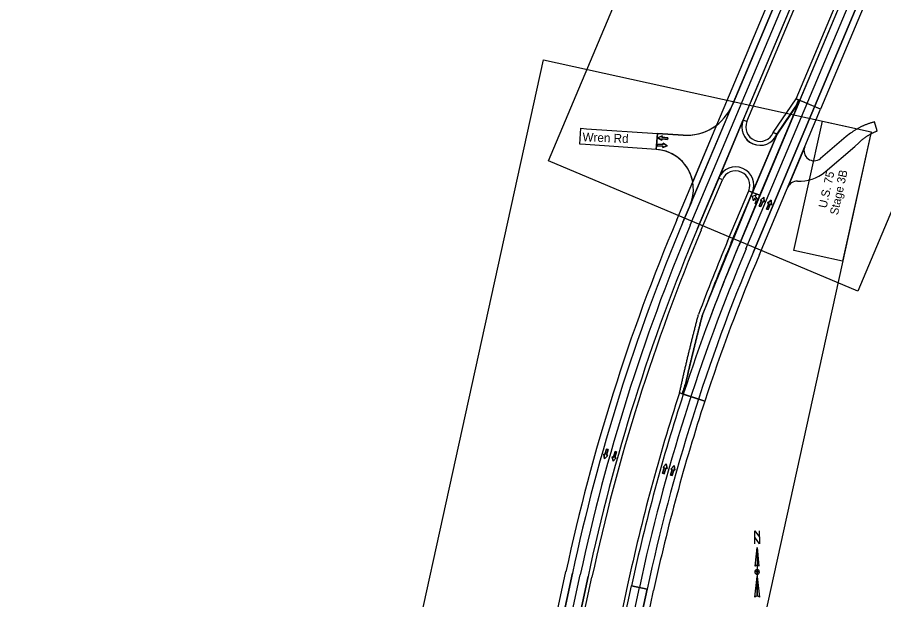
# Model space of a CAD drawing. Extents: x 14104283 to 14120882, y 8635219 to 8671666.
# Drawn here: x 14108141 to 14109445, y 8644864 to 8645740 of the extents above; entities that cross this region are included whole.
import ezdxf

# ---------------------------------------------------------------- set-up
doc = ezdxf.new("R2010")
doc.units = 0
for name, color, linetype in [('Cell', 7, 'Continuous'), ('dsnCellsNorthArrow', 7, 'Continuous'), ('dsnNonPlotable', 7, 'Continuous'), ('dsnPaintExistingBrokenLaneLineWhite', 7, 'Continuous'), ('dsnPaintExistingEdgeLineLeftYellow', 7, 'Continuous'), ('dsnPaintExistingEdgeLineRightWhite', 7, 'Continuous'), ('dsnPaintExistingLaneLineWhite', 7, 'Continuous'), ('dsnShadingGranular', 7, 'Continuous'), ('dsnShadingPaved', 7, 'Continuous'), ('dsnStgShadingPrevPav', 7, 'Continuous'), ('dsnTextFinalPlan', 7, 'Continuous'), ('dsnTextOverlapEven', 7, 'Continuous')]:
    doc.layers.add(name, color=color, linetype=linetype)

msp = doc.modelspace()

# ---------------------------------------------------------------- linework, layer by layer
at = {"layer": 'Cell'}
for p, q in [((14109250.7, 8645466.9), (14109250.4, 8645467)), ((14109251.5, 8645469.4), (14109251.7, 8645469.4))]:
    msp.add_line(p, q, dxfattribs=at)
for points in [[(14109119.8, 8645558.6), (14109119.6, 8645556.1), (14109110.9, 8645556.8), (14109110.7, 8645554.9), (14109104.8, 8645558.6), (14109111.2, 8645561.2), (14109111.1, 8645559.3)], [(14109103.8, 8645546.5), (14109104, 8645549), (14109112.7, 8645548.3), (14109112.9, 8645550.1), (14109118.9, 8645546.5), (14109112.4, 8645543.9), (14109112.5, 8645545.8)], [(14109259.9, 8645454.9), (14109257.6, 8645455.8), (14109260.9, 8645463.9), (14109259.2, 8645464.6), (14109264.4, 8645469.2), (14109265, 8645462.3), (14109263.2, 8645463)], [(14109270.7, 8645450.4), (14109268.4, 8645451.3), (14109271.7, 8645459.4), (14109270, 8645460.1), (14109275.2, 8645464.7), (14109275.7, 8645457.7), (14109274, 8645458.5)], [(14109027.8, 8645090.4), (14109030.2, 8645089.7), (14109027.7, 8645081.3), (14109029.5, 8645080.7), (14109024.8, 8645075.6), (14109023.5, 8645082.5), (14109025.3, 8645082)], [(14109040.4, 8645086.8), (14109042.8, 8645086.1), (14109040.3, 8645077.7), (14109042.1, 8645077.2), (14109037.4, 8645072.1), (14109036.1, 8645078.9), (14109037.9, 8645078.4)], [(14109114.4, 8645053.2), (14109112, 8645054), (14109114.5, 8645062.3), (14109112.7, 8645062.9), (14109117.4, 8645068), (14109118.7, 8645061.1), (14109116.9, 8645061.6)], [(14109126.3, 8645050.6), (14109123.9, 8645051.3), (14109126.3, 8645059.7), (14109124.5, 8645060.3), (14109129.3, 8645065.4), (14109130.5, 8645058.5), (14109128.7, 8645059)]]:
    msp.add_lwpolyline(points, close=True, dxfattribs=at)
for points in [[(14109111.1, 8645559.3), (14109111.2, 8645561.2), (14109104.8, 8645558.6), (14109110.7, 8645554.9), (14109110.9, 8645556.8), (14109119.6, 8645556.1), (14109119.8, 8645558.6), (14109111.1, 8645559.3)], [(14109112.5, 8645545.8), (14109112.4, 8645543.9), (14109118.9, 8645546.5), (14109112.9, 8645550.1), (14109112.7, 8645548.3), (14109104, 8645549), (14109103.8, 8645546.5), (14109112.5, 8645545.8)], [(14109247.3, 8645470.5), (14109253, 8645472.8), (14109251.5, 8645469.4)], [(14109247.3, 8645470.5), (14109253, 8645472.8), (14109251.5, 8645469.4)], [(14109250.4, 8645467), (14109248.8, 8645463.7), (14109247.3, 8645470.5)], [(14109250.4, 8645467), (14109248.8, 8645463.7), (14109247.3, 8645470.5)], [(14109250.7, 8645466.9), (14109250.4, 8645467)], [(14109251.5, 8645469.4), (14109251.7, 8645469.4)], [(14109263.2, 8645463), (14109265, 8645462.3), (14109264.4, 8645469.2), (14109259.2, 8645464.6), (14109260.9, 8645463.9), (14109257.6, 8645455.8), (14109259.9, 8645454.9), (14109263.2, 8645463)], [(14109274, 8645458.5), (14109275.7, 8645457.7), (14109275.2, 8645464.7), (14109270, 8645460.1), (14109271.7, 8645459.4), (14109268.4, 8645451.3), (14109270.7, 8645450.4), (14109274, 8645458.5)], [(14109254.3, 8645462.6), (14109252.9, 8645459.2), (14109251.5, 8645459.8), (14109252.5, 8645462.2)], [(14109254.3, 8645462.6), (14109252.9, 8645459.2), (14109251.5, 8645459.8), (14109252.5, 8645462.2)], [(14109025.3, 8645082), (14109023.5, 8645082.5), (14109024.8, 8645075.6), (14109029.5, 8645080.7), (14109027.7, 8645081.3), (14109030.2, 8645089.7), (14109027.8, 8645090.4), (14109025.3, 8645082)], [(14109037.9, 8645078.4), (14109036.1, 8645078.9), (14109037.4, 8645072.1), (14109042.1, 8645077.2), (14109040.3, 8645077.7), (14109042.8, 8645086.1), (14109040.4, 8645086.8), (14109037.9, 8645078.4)], [(14109116.9, 8645061.6), (14109118.7, 8645061.1), (14109117.4, 8645068), (14109112.7, 8645062.9), (14109114.5, 8645062.3), (14109112, 8645054), (14109114.4, 8645053.2), (14109116.9, 8645061.6)], [(14109128.7, 8645059), (14109130.5, 8645058.5), (14109129.3, 8645065.4), (14109124.5, 8645060.3), (14109126.3, 8645059.7), (14109123.9, 8645051.3), (14109126.3, 8645050.6), (14109128.7, 8645059)]]:
    msp.add_lwpolyline(points, dxfattribs=at)
for centre, major_axis in [((14109249.3, 8645463.5), (-1.38, -3.41)), ((14109249.3, 8645463.5), (-1.38, -3.41)), ((14109249.7, 8645464.5), (-1.97, -4.87)), ((14109249.7, 8645464.5), (-1.97, -4.87))]:
    msp.add_ellipse(centre, major_axis=major_axis, ratio=0.9474, start_param=1.570796, end_param=3.141593, dxfattribs=at)
at = {"layer": 'dsnCellsNorthArrow'}
for p, q in [((14109254.3, 8644942.2), (14109257.1, 8644914.1)), ((14109254.3, 8644942.2), (14109254.3, 8644869)), ((14109251.5, 8644914.1), (14109251.5, 8644914.1)), ((14109251.6, 8644914.3), (14109252.1, 8644914.9)), ((14109250.8, 8644867.6), (14109254.3, 8644898.6)), ((14109254.3, 8644902.1), (14109254.3, 8644902.1))]:
    msp.add_line(p, q, dxfattribs=at)
msp.add_lwpolyline([(14109257.8, 8644947.9), (14109250.8, 8644957.7), (14109250.8, 8644967.6), (14109257.8, 8644957.7)], close=True, dxfattribs=at)
for points in [[(14109250.8, 8644947.9), (14109250.8, 8644967.6), (14109257.8, 8644957.7), (14109257.8, 8644967.6)], [(14109251.5, 8644914.1), (14109254.3, 8644942.2), (14109254.3, 8644915.5)], [(14109254.3, 8644902.1), (14109254.3, 8644905.6), (14109250.8, 8644905.6)], [(14109257.8, 8644905.6), (14109254.3, 8644905.6), (14109254.3, 8644909.1)], [(14109254.3, 8644869), (14109254.3, 8644898.6), (14109257.8, 8644867.6)]]:
    msp.add_lwpolyline(points, dxfattribs=at)
for centre, radius, start, end in [((14109254.3, 8644905.6), 3.52, 90, 180), ((14109254.3, 8644905.6), 3.52, 180, 270), ((14109254.3, 8644912), 3.52, 90.0204, 143.1257), ((14109254.3, 8644912), 3.52, 36.8481, 90.0218), ((14109254.3, 8644905.6), 3.52, 0, 90), ((14109254.3, 8644905.6), 3.52, 270, 360), ((14109254.3, 8644863.9), 5.1, 89.9894, 133.619), ((14109254.3, 8644863.9), 5.11, 46.4021, 90.0006)]:
    msp.add_arc(centre, radius, start, end, dxfattribs=at)
at = {"layer": 'dsnNonPlotable'}
for points in [[(14108940.5, 8645523.8), (14109549.1, 8646968.3), (14110014.5, 8646772.2), (14109405.9, 8645327.7)], [(14108596.1, 8644144.9), (14108932.5, 8645675.8), (14109425.7, 8645567.5), (14109089.3, 8644036.5)]]:
    msp.add_lwpolyline(points, close=True, dxfattribs=at)
at = {"layer": 'dsnPaintExistingBrokenLaneLineWhite'}
for p, q in [((14109153.7, 8645426.8), (14110829.5, 8649404.5)), ((14109237.5, 8645391.4), (14110075.4, 8647380.3)), ((14108623.3, 8643207.7), (14108988, 8644901.3))]:
    msp.add_line(p, q, dxfattribs=at)
msp.add_lwpolyline([(14108306.4, 8641340.7), (14108389, 8641717), (14108712.3, 8643188.3), (14108894.6, 8644035.3), (14109077, 8644882.2)], dxfattribs=at)
for radius in [2956, 2865]:
    msp.add_arc((14111877.8, 8644279.1), radius, 157.1547, 167.8488, dxfattribs=at)
at = {"layer": 'dsnPaintExistingEdgeLineLeftYellow'}
for p, q in [((14109318.5, 8645614.6), (14110902.3, 8649373.8)), ((14109283.6, 8645562.9), (14109318.3, 8645614.1)), ((14109196.6, 8645497.8), (14109164.7, 8645422.1)), ((14109171.7, 8645290.7), (14109247.3, 8645476.4)), ((14109143.1, 8645172.8), (14109171.7, 8645290.7)), ((14108700.5, 8643190.8), (14109065.3, 8644884.7))]:
    msp.add_line(p, q, dxfattribs=at)
for points in [[(14111383.6, 8650689.4), (14110840.5, 8649399.8), (14109233.5, 8645585.3)], [(14108999.8, 8644898.8), (14108635.1, 8643205.1), (14108434.9, 8642294.1)]]:
    msp.add_lwpolyline(points, dxfattribs=at)
for centre, radius, start, end in [((14109258.8, 8645574.6), 27.5, 157.1547, 335.8415), ((14109221.9, 8645487.1), 27.5, 67.1547, 157.1547), ((14109221.9, 8645487.1), 27.5, 337.1547, 67.1547), ((14111877.8, 8644279.1), 2944, 157.1547, 167.8488), ((14111877.8, 8644279.1), 2877, 161.903, 167.8488)]:
    msp.add_arc(centre, radius, start, end, dxfattribs=at)
at = {"layer": 'dsnPaintExistingEdgeLineRightWhite'}
for p, q in [((14109248.6, 8645386.8), (14110924.4, 8649364.5)), ((14109155.3, 8645461.5), (14109142.6, 8645431.4)), ((14108724, 8643185.8), (14109088.7, 8644879.7))]:
    msp.add_line(p, q, dxfattribs=at)
for points in [[(14111344.6, 8650658.6), (14110818.4, 8649409.2), (14109217, 8645608.1)], [(14108976.3, 8644903.9), (14108611.6, 8643210.2), (14108202.1, 8641346.1)]]:
    msp.add_lwpolyline(points, dxfattribs=at)
for radius in [2968, 2853]:
    msp.add_arc((14111877.8, 8644279.1), radius, 157.1547, 167.8488, dxfattribs=at)
at = {"layer": 'dsnPaintExistingLaneLineWhite'}
msp.add_line((14109226.5, 8645396.1), (14109258.5, 8645472.2), dxfattribs=at)
msp.add_arc((14111877.8, 8644279.1), 2877, 157.1547, 159.5027, dxfattribs=at)
at = {"layer": 'dsnShadingGranular'}
msp.add_line((14109326, 8645544.7), (14109300.4, 8645484), dxfattribs=at)
at = {"layer": 'dsnShadingPaved'}
for p, q in [((14110924.4, 8649364.5), (14109248.6, 8645386.8)), ((14109258.5, 8645472.2), (14110902.3, 8649373.8)), ((14109153.7, 8645457.8), (14109217, 8645608.1)), ((14109318.3, 8645614.1), (14109258.5, 8645472.2)), ((14109283.6, 8645562.9), (14109318.3, 8645614.1)), ((14109196.6, 8645497.8), (14109233.5, 8645585.3)), ((14109104.1, 8645564.9), (14109102.5, 8645541)), ((14109142.9, 8645562.3), (14109104.1, 8645564.9)), ((14109171.7, 8645290.7), (14109247.3, 8645476.4)), ((14109247.3, 8645476.4), (14109258.5, 8645472.2)), ((14109258.5, 8645472.2), (14109247.3, 8645476.4)), ((14109143.1, 8645172.8), (14109171.7, 8645290.7)), ((14108700.5, 8643190.8), (14109065.3, 8644884.7)), ((14109088.7, 8644879.7), (14108724, 8643185.8)), ((14109065.3, 8644884.7), (14109088.7, 8644879.7)), ((14109088.7, 8644879.7), (14109065.3, 8644884.7))]:
    msp.add_line(p, q, dxfattribs=at)
for points in [[(14118413.2, 8667444.3), (14110818.4, 8649409.2), (14109142.6, 8645431.4)], [(14109164.7, 8645422.1), (14110840.5, 8649399.8), (14118435.4, 8667434.9)], [(14108976.3, 8644903.9), (14108611.6, 8643210.2), (14108202.1, 8641346.1)], [(14108434.9, 8642294.1), (14108635.1, 8643205.1), (14108999.8, 8644898.8)]]:
    msp.add_lwpolyline(points, dxfattribs=at)
for centre, radius, start, end in [((14109147.9, 8645637.2), 75, 266.1547, 337.1547), ((14109258.8, 8645574.6), 27.5, 157.1547, 247.1547), ((14109258.8, 8645574.6), 27.5, 247.1547, 335.8415), ((14109098.4, 8645481.1), 60, 337.1547, 86.1547), ((14109221.9, 8645487.1), 27.5, 67.1547, 157.1547), ((14109221.9, 8645487.1), 27.5, 337.1547, 67.1547), ((14111877.8, 8644279.1), 2968, 157.1547, 167.8488), ((14111877.8, 8644279.1), 2944, 157.1547, 167.8488), ((14111877.8, 8644279.1), 2853, 157.1547, 167.8488), ((14111877.8, 8644279.1), 2877, 161.903, 167.8488)]:
    msp.add_arc(centre, radius, start, end, dxfattribs=at)
at = {"layer": 'dsnStgShadingPrevPav'}
for p, q in [((14109133.4, 8645435.3), (14110809.2, 8649413)), ((14110818.4, 8649409.2), (14109142.6, 8645431.4)), ((14109155.3, 8645461.5), (14109217, 8645608.1)), ((14109318.5, 8645614.6), (14109226.5, 8645396.1)), ((14109318.5, 8645614.6), (14109226.5, 8645396.1)), ((14109312.8, 8645606.2), (14109316.7, 8645615.4)), ((14109316.7, 8645615.4), (14109318.5, 8645614.6)), ((14109349.9, 8645601.4), (14109318.5, 8645614.6)), ((14109257.8, 8645382.9), (14109349.9, 8645601.4)), ((14109284.2, 8645564), (14109312.8, 8645606.2)), ((14109196.6, 8645497.8), (14109233.5, 8645585.3)), ((14109233.5, 8645585.3), (14109196.6, 8645497.8)), ((14109233.5, 8645585.3), (14109239, 8645583)), ((14109435.2, 8645568.8), (14109431.1, 8645582.2)), ((14109193.3, 8645577.5), (14109157.4, 8645492.3)), ((14109102.5, 8645541), (14109104.1, 8645564.9)), ((14109104.1, 8645564.9), (14109142.9, 8645562.3)), ((14109215.4, 8645400.8), (14109284.2, 8645564)), ((14109284.2, 8645564), (14109247.3, 8645476.4)), ((14109278.6, 8645566.3), (14109284.2, 8645564)), ((14109326, 8645544.7), (14109300.4, 8645484)), ((14109356.6, 8645507.3), (14109401.4, 8645545.2)), ((14109401.4, 8645545.2), (14109407.2, 8645550.9)), ((14109196.6, 8645497.8), (14109164.7, 8645422.1)), ((14109196.6, 8645497.8), (14109164.7, 8645422.1)), ((14109170.3, 8645419.8), (14109202.1, 8645495.4)), ((14109202.1, 8645495.4), (14109196.6, 8645497.8)), ((14109202.1, 8645495.4), (14109196.6, 8645497.8)), ((14109209.9, 8645403.1), (14109241.8, 8645478.7)), ((14109247.3, 8645476.4), (14109241.8, 8645478.7)), ((14109241.8, 8645478.7), (14109247.3, 8645476.4)), ((14109247.3, 8645476.4), (14109215.4, 8645400.8)), ((14109142.6, 8645431.4), (14109155.3, 8645461.5)), ((14109175.4, 8645162.3), (14109137.4, 8645174.7)), ((14109141.2, 8645173.4), (14109137.4, 8645174.7)), ((14109143.1, 8645172.8), (14109141.2, 8645173.4)), ((14109143.1, 8645172.8), (14109175.4, 8645162.3)), ((14108601.8, 8643212.3), (14108966.5, 8644906)), ((14108976.3, 8644903.9), (14108611.6, 8643210.2)), ((14109059.4, 8644886), (14108694.7, 8643192.1)), ((14108733.8, 8643183.6), (14109098.5, 8644877.6))]:
    msp.add_line(p, q, dxfattribs=at)
for points in [[(14109239, 8645583), (14111389.1, 8650687.1), (14111383.6, 8650689.4), (14109233.5, 8645585.3)], [(14109313, 8645616.9), (14110622.7, 8648725.7), (14110659.7, 8648710.5), (14109349.9, 8645601.4)], [(14109278.6, 8645566.3), (14109313, 8645616.9), (14109316.7, 8645615.4), (14109312.8, 8645606.2), (14109284.2, 8645564)], [(14108987.2, 8645548.7), (14108988.7, 8645572.7), (14108997.4, 8645572.1), (14109104.1, 8645564.9), (14109102.5, 8645541), (14108995.8, 8645548.2)]]:
    msp.add_lwpolyline(points, close=True, dxfattribs=at)
for points in [[(14111383.6, 8650689.4), (14110840.5, 8649399.8), (14109233.5, 8645585.3)], [(14109217, 8645608.1), (14110818.4, 8649409.2), (14111344.6, 8650658.6)], [(14109395, 8645565.3), (14109388.4, 8645560.5), (14109349.5, 8645527.5)], [(14108202.1, 8641346.1), (14108611.6, 8643210.2), (14108976.3, 8644903.9)], [(14108999.8, 8644898.8), (14108817.4, 8644052), (14108635.1, 8643205.1), (14108387.9, 8642080.1), (14108140.8, 8640955.1)], [(14108146.7, 8640953.8), (14108640.9, 8643203.9), (14109005.6, 8644897.6)], [(14108999.8, 8644898.8), (14108635.1, 8643205.1), (14108225.5, 8641340.9)]]:
    msp.add_lwpolyline(points, dxfattribs=at)
for centre, radius, start, end in [((14109258.8, 8645574.6), 21.5, 157.1547, 247.1547), ((14109147.9, 8645637.2), 75, 266.1547, 307.2283), ((14109258.8, 8645574.6), 21.5, 247.1547, 337.1547), ((14109339.8, 8645538.9), 15, 157.1547, 310.2778), ((14109098.4, 8645481.1), 60, 10.712, 86.1547), ((14109221.9, 8645487.1), 21.5, 67.1547, 157.1547), ((14109221.9, 8645487.1), 21.5, 337.1547, 67.1547), ((14109317.8, 8645553), 60, 267.2336, 310.2778), ((14109314.2, 8645478.1), 15, 87.2336, 157.1547), ((14111877.8, 8644279.1), 2978, 157.1547, 167.8488), ((14111877.8, 8644279.1), 2968, 157.1547, 167.8488), ((14111877.8, 8644279.1), 2968, 157.1547, 167.8488), ((14111877.8, 8644279.1), 2944, 157.1547, 167.8488), ((14111877.8, 8644279.1), 2944, 157.1547, 167.8488), ((14111877.8, 8644279.1), 2938, 157.1547, 167.8488), ((14111877.8, 8644279.1), 2895, 157.1547, 159.5027), ((14111877.8, 8644279.1), 2889, 157.1547, 159.5027), ((14111877.8, 8644279.1), 2889, 157.1547, 159.5027), ((14111877.8, 8644279.1), 2877, 157.1547, 161.9025), ((14111877.8, 8644279.1), 2877, 157.1547, 161.9025), ((14111877.8, 8644279.1), 2843, 157.1547, 161.9025), ((14111877.8, 8644279.1), 2879, 161.5026, 161.9025), ((14111877.8, 8644279.1), 2879, 161.5026, 161.9025), ((14111877.8, 8644279.1), 2883, 161.9025, 167.8488), ((14111877.8, 8644279.1), 2843, 161.9025, 167.8488)]:
    msp.add_arc(centre, radius, start, end, dxfattribs=at)
for points in [[(14109431.1, 8645582.2), (14109430.5, 8645582.1), (14109429.2, 8645581.8), (14109427.3, 8645581.3), (14109425.4, 8645580.7), (14109423.5, 8645580.1), (14109421.6, 8645579.5), (14109419.7, 8645578.8), (14109417.8, 8645578.1), (14109416, 8645577.3), (14109414.1, 8645576.5), (14109412.3, 8645575.7), (14109410.5, 8645574.8), (14109408.7, 8645573.9), (14109406.9, 8645573), (14109405.1, 8645572), (14109403.4, 8645571), (14109401.7, 8645569.9), (14109400, 8645568.8), (14109398.3, 8645567.7), (14109396.6, 8645566.5), (14109395.5, 8645565.7), (14109395, 8645565.3)], [(14109407.2, 8645550.9), (14109407.6, 8645551.3), (14109408.4, 8645552), (14109409.6, 8645553.1), (14109410.9, 8645554.2), (14109412.1, 8645555.3), (14109413.4, 8645556.4), (14109414.7, 8645557.4), (14109416, 8645558.4), (14109417.4, 8645559.4), (14109418.8, 8645560.3), (14109420.2, 8645561.2), (14109421.6, 8645562.1), (14109423, 8645563), (14109424.5, 8645563.8), (14109426, 8645564.6), (14109427.5, 8645565.4), (14109429, 8645566.2), (14109430.5, 8645566.9), (14109432, 8645567.6), (14109433.6, 8645568.2), (14109434.7, 8645568.6), (14109435.2, 8645568.8)], [(14109137.4, 8645174.7), (14109137.9, 8645176.7), (14109138.7, 8645180.6), (14109140.1, 8645186.5), (14109141.4, 8645192.5), (14109142.7, 8645198.4), (14109144.1, 8645204.3), (14109145.5, 8645210.2), (14109146.9, 8645216.1), (14109148.3, 8645222), (14109149.7, 8645228), (14109151.1, 8645233.9), (14109152.5, 8645239.8), (14109154, 8645245.7), (14109155.5, 8645251.6), (14109156.9, 8645257.5), (14109158.4, 8645263.4), (14109159.9, 8645269.3), (14109161.5, 8645275.2), (14109163, 8645281.1), (14109164.5, 8645287), (14109165.6, 8645290.9), (14109166.1, 8645292.8)], [(14109147.5, 8645192.5), (14109147.9, 8645194.2), (14109148.7, 8645197.4), (14109149.8, 8645202.4), (14109150.9, 8645207.3), (14109152.1, 8645212.2), (14109153.2, 8645217.1), (14109154.4, 8645222), (14109155.6, 8645227), (14109156.8, 8645231.9), (14109158, 8645236.8), (14109159.2, 8645241.7), (14109160.4, 8645246.6), (14109161.6, 8645251.5), (14109162.8, 8645256.4), (14109164.1, 8645261.3), (14109165.3, 8645266.2), (14109166.6, 8645271.1), (14109167.8, 8645276), (14109169.1, 8645281), (14109170.4, 8645285.9), (14109171.3, 8645289.1), (14109171.7, 8645290.7)], [(14109171.7, 8645290.7), (14109171.3, 8645289.1), (14109170.4, 8645285.9), (14109169.1, 8645281), (14109167.8, 8645276), (14109166.6, 8645271.1), (14109165.3, 8645266.2), (14109164.1, 8645261.3), (14109162.8, 8645256.4), (14109161.6, 8645251.5), (14109160.4, 8645246.6), (14109159.2, 8645241.7), (14109158, 8645236.8), (14109156.8, 8645231.9), (14109155.6, 8645227), (14109154.4, 8645222), (14109153.2, 8645217.1), (14109152.1, 8645212.2), (14109150.9, 8645207.3), (14109149.8, 8645202.4), (14109148.7, 8645197.4), (14109147.9, 8645194.2), (14109147.5, 8645192.5)]]:
    msp.add_open_spline(points, degree=3, dxfattribs=at)
at = {"layer": 'dsnTextOverlapEven'}
for points in [[(14109425.7, 8645567.5), (14109383, 8645372.8), (14109309.7, 8645388.9), (14109352.5, 8645583.6)], [(14109309.7, 8645388.9), (14109352.5, 8645583.6), (14109425.7, 8645567.5), (14109383, 8645372.8)]]:
    msp.add_lwpolyline(points, close=True, dxfattribs=at)

# ---------------------------------------------------------------- texts
at = {"layer": 'dsnTextFinalPlan'}
msp.add_text('Wren Rd', height=13.12, rotation=357.6374, dxfattribs=at).set_placement((14108991.3, 8645553.3))
at = {"layer": 'dsnTextOverlapEven'}
for s, p in [('U.S. 75', (14109358.7, 8645451.9)), ('Stage 3B', (14109375.7, 8645441.5))]:
    msp.add_text(s, height=12.5, rotation=77.6078, dxfattribs=at).set_placement(p)

doc.saveas('drawing.dxf')
